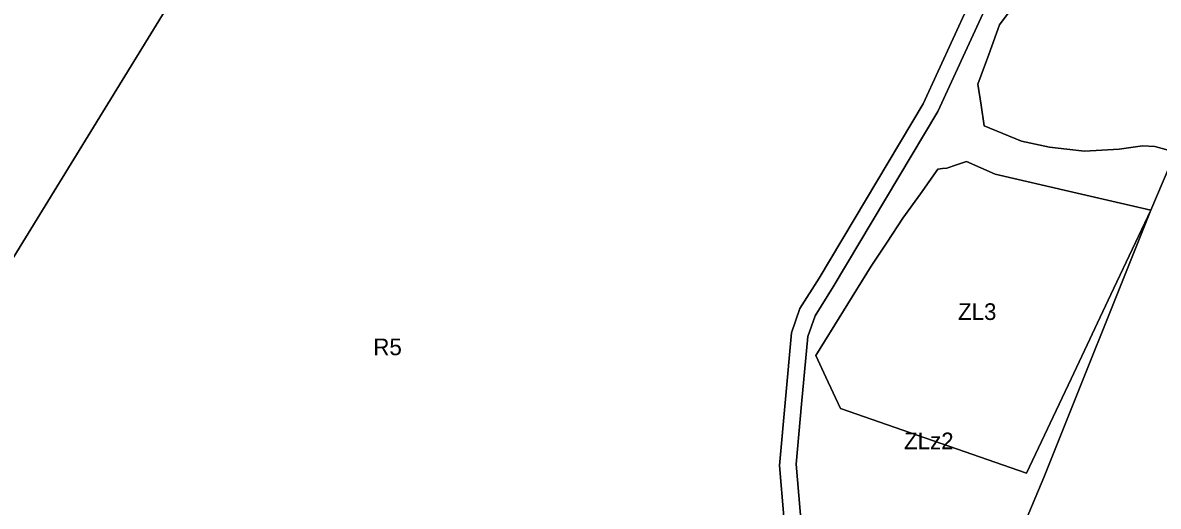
# Model space of a CAD drawing. Extents: x 7439486 to 7443435, y 5551288 to 5554556.
# Drawn here: x 7441056 to 7441738, y 5552613 to 5552904 of the extents above; entities that cross this region are included whole.
import ezdxf

# ---------------------------------------------------------------- set-up
doc = ezdxf.new("R2010")
doc.units = 0
doc.layers.add('linie_rozgraniczajace', color=7, linetype='Continuous')
doc.layers.add('oznaczenia_przeznaczen', color=7, linetype='Continuous')

msp = doc.modelspace()

# ---------------------------------------------------------------- linework, layer by layer
at = {"layer": 'linie_rozgraniczajace'}
for points in [[(7440784.09, 5552438.75), (7440788.29, 5552442.28), (7440796.71, 5552449.34), (7440805.16, 5552456.78), (7440813.62, 5552464.22), (7440822.38, 5552472.46), (7440831.14, 5552480.7), (7440841.01, 5552490.47), (7440850.87, 5552500.24), (7440860.32, 5552509.94), (7440861.3, 5552510.94), (7440872.68, 5552522.16), (7440937.87, 5552579.63), (7441018.76, 5552711.22), (7441030.31, 5552730.01), (7441199.76, 5553005.69)], [(7441199.76, 5553005.69), (7441030.31, 5552730.01), (7441018.76, 5552711.22), (7440937.87, 5552579.63), (7440872.68, 5552522.16), (7440861.3, 5552510.94), (7440860.32, 5552509.94), (7440850.87, 5552500.24), (7440841.01, 5552490.47), (7440831.14, 5552480.7), (7440822.38, 5552472.46), (7440813.62, 5552464.22), (7440805.16, 5552456.78), (7440796.71, 5552449.34), (7440788.29, 5552442.28), (7440784.09, 5552438.75), (7440811.19, 5552387.81), (7440863.47, 5552293.77), (7440866.42, 5552287.9), (7440881.12, 5552260.61), (7440890.03, 5552241.86), (7440895.39, 5552221.28), (7440904.26, 5552212.34)], [(7441623.69, 5552913.88), (7441596.56, 5552855.07), (7441534.12, 5552750.43), (7441522.65, 5552732.1), (7441517.56, 5552717.49), (7441510.43, 5552637.85), (7441513.04, 5552607.04)], [(7441513.04, 5552607.04), (7441510.43, 5552637.85), (7441517.56, 5552717.49), (7441522.65, 5552732.1), (7441534.12, 5552750.43), (7441596.56, 5552855.07), (7441623.69, 5552913.88)], [(7441632.49, 5552909.09), (7441605.42, 5552850.4), (7441542.65, 5552745.21), (7441531.72, 5552727.75), (7441527.41, 5552715.36), (7441523.69, 5552674.78), (7441520.39, 5552638.69), (7441525.97, 5552572.89), (7441522.44, 5552558.06), (7441484.47, 5552476.5), (7441475.68, 5552466.97), (7441471.28, 5552462.21), (7441466.88, 5552457.45)], [(7441525.97, 5552572.89), (7441520.39, 5552638.69), (7441523.69, 5552674.78), (7441527.41, 5552715.36), (7441531.72, 5552727.75), (7441542.65, 5552745.21), (7441605.42, 5552850.4), (7441632.49, 5552909.09)], [(7441648.31, 5552910.37), (7441642.52, 5552902.6), (7441635.94, 5552884.73), (7441629.36, 5552866.87), (7441631.34, 5552854.32), (7441633.32, 5552841.77), (7441655.59, 5552832.59), (7441664, 5552830.85), (7441672.41, 5552829.12), (7441682.92, 5552827.91), (7441693.43, 5552826.7), (7441703.85, 5552827.27), (7441714.27, 5552827.83), (7441721.28, 5552828.89), (7441728.29, 5552829.94), (7441735.68, 5552829.38), (7441747.99, 5552826), (7441733.17, 5552791.22), (7441686.46, 5552802.06), (7441639.75, 5552812.9), (7441622.59, 5552820.51), (7441616.71, 5552818.51), (7441610.84, 5552816.51), (7441608.16, 5552816.14), (7441605.47, 5552815.76), (7441594.95, 5552801.12), (7441584.42, 5552786.49), (7441574.96, 5552772.03), (7441565.49, 5552757.56), (7441548.82, 5552730.8), (7441532.15, 5552704.04), (7441538.22, 5552690.87), (7441546.97, 5552672.13), (7441602.76, 5552652.67), (7441658.55, 5552633.21), (7441685.43, 5552689.99), (7441709.3, 5552740.61), (7441733.17, 5552791.22), (7441668.96, 5552630.65), (7441656.87, 5552601.68)], [(7441629.36, 5552866.87), (7441635.94, 5552884.73), (7441642.52, 5552902.6), (7441648.31, 5552910.37)], [(7441760.3, 5552862.05), (7441754.14, 5552844.03), (7441747.99, 5552826), (7441735.68, 5552829.38), (7441728.29, 5552829.94), (7441721.28, 5552828.89), (7441714.27, 5552827.83), (7441703.85, 5552827.27), (7441693.43, 5552826.7), (7441682.92, 5552827.91), (7441672.41, 5552829.12), (7441664, 5552830.85), (7441655.59, 5552832.59), (7441633.32, 5552841.77), (7441631.34, 5552854.32), (7441629.36, 5552866.87)], [(7441473.89, 5552135.18), (7441499.22, 5552283.92), (7441504.07, 5552316.14), (7441505.1, 5552320.35), (7441540.55, 5552355.88), (7441551.52, 5552368.86), (7441550.62, 5552385.33), (7441556.44, 5552402.45), (7441576.8, 5552425.65), (7441584.14, 5552441.59), (7441602.31, 5552461.23), (7441611.94, 5552480.61), (7441612.56, 5552494.07), (7441620.35, 5552507.59), (7441627.86, 5552516.46), (7441629.87, 5552523.95), (7441627.21, 5552530.83), (7441656.87, 5552601.68), (7441668.96, 5552630.65), (7441733.17, 5552791.22), (7441747.99, 5552826)]]:
    msp.add_lwpolyline(points, dxfattribs=at)
msp.add_lwpolyline([(7441532.15, 5552704.04), (7441548.82, 5552730.8), (7441565.49, 5552757.56), (7441574.96, 5552772.03), (7441584.42, 5552786.49), (7441594.95, 5552801.12), (7441605.47, 5552815.76), (7441608.16, 5552816.14), (7441610.84, 5552816.51), (7441616.71, 5552818.51), (7441622.59, 5552820.51), (7441639.75, 5552812.9), (7441686.46, 5552802.06), (7441733.17, 5552791.22), (7441709.3, 5552740.61), (7441685.43, 5552689.99), (7441658.55, 5552633.21), (7441602.76, 5552652.67), (7441546.97, 5552672.13), (7441538.22, 5552690.87)], close=True, dxfattribs=at)

# ---------------------------------------------------------------- texts
at = {"layer": 'oznaczenia_przeznaczen'}
for s, p in [('ZL3', (7441617.53, 5552725.28)), ('R5', (7441266.69, 5552704.11)), ('ZLz2', (7441585.16, 5552647.67))]:
    msp.add_text(s, height=10, dxfattribs=at).set_placement(p)

doc.saveas('drawing.dxf')
